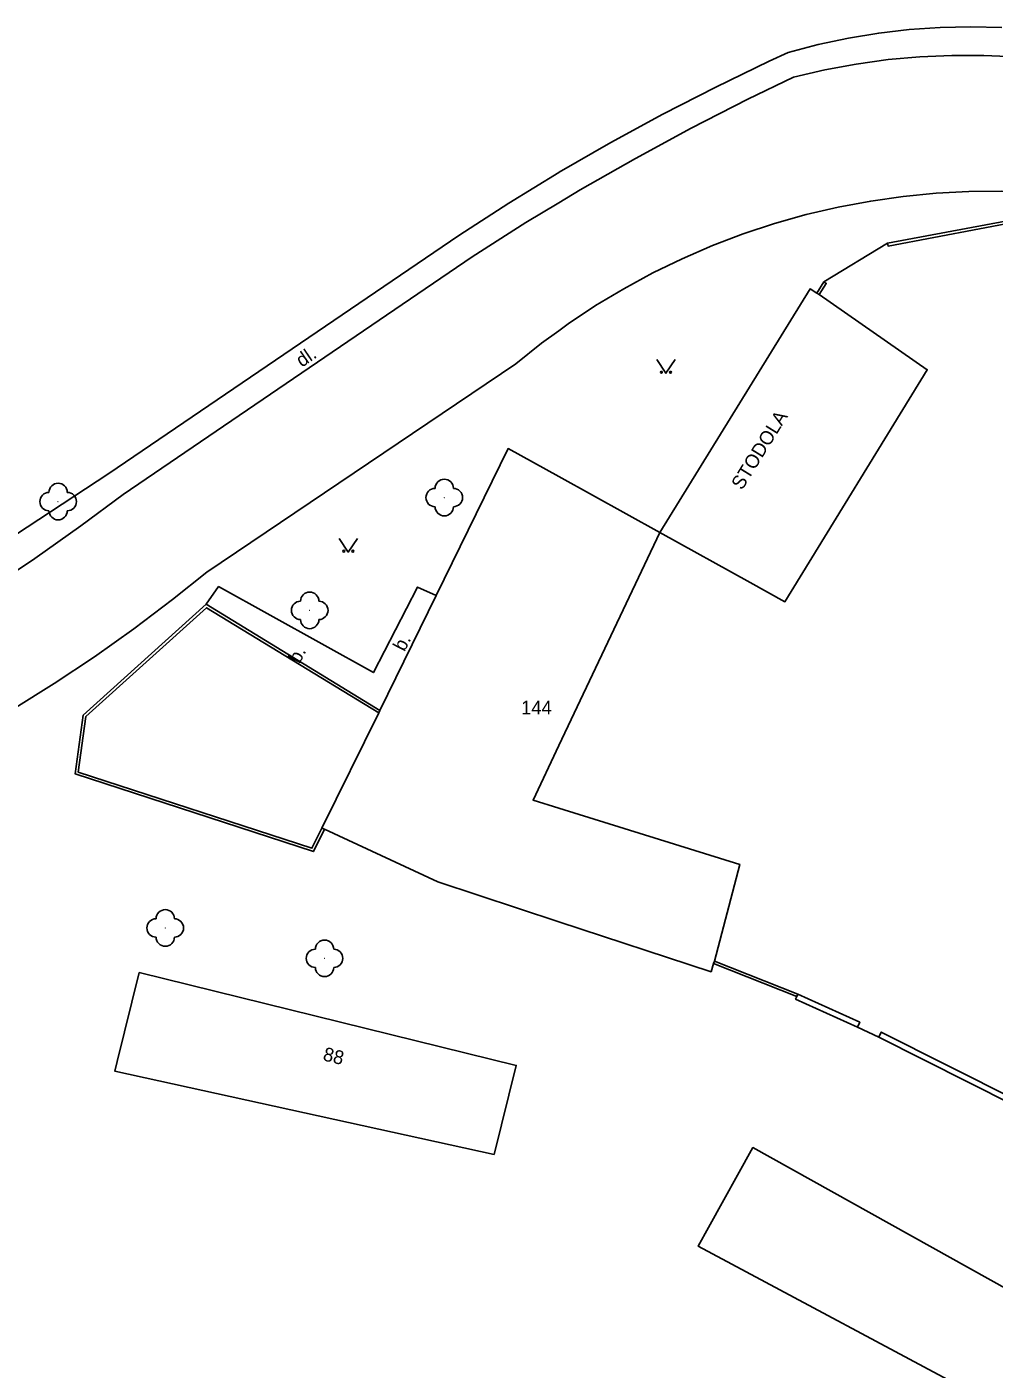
# Model space of a CAD drawing. Extents: x -582162 to -561283, y -1187583 to -1183539.
# Drawn here: x -570029.1 to -569976.2, y -1185373.8 to -1185300.5 of the extents above; entities that cross this region are included whole.
import ezdxf

# ---------------------------------------------------------------- set-up
doc = ezdxf.new("R2010")
doc.units = 0
for name, color, linetype in [('Vrstva 1', 7, 'Continuous'), ('Vrstva 10', 7, 'Continuous'), ('Vrstva 11', 7, 'Continuous'), ('Vrstva 14', 7, 'Continuous'), ('Vrstva 3', 7, 'Continuous'), ('Vrstva 4', 7, 'Continuous'), ('Vrstva 5', 7, 'Continuous'), ('Vrstva 6', 7, 'Continuous'), ('Vrstva 9', 7, 'Continuous')]:
    doc.layers.add(name, color=color, linetype=linetype)

# ---------------------------------------------------------------- blocks, each defined once
blk = doc.blocks.new('3.130')
at = {"layer": 'Vrstva 1'}
blk.add_circle((0, 0), 0.001, dxfattribs=at)
for centre, start, end in [((0, 1), 0, 180), ((-1, 0), 90, 270), ((1, 0), 270, 90), ((0, -1), 180, 360)]:
    blk.add_arc(centre, 1, start, end, dxfattribs=at)
blk = doc.blocks.new('3.140')
at = {"layer": 'Vrstva 1'}
blk.add_lwpolyline([(-1, 1.5), (0, 0), (1, 1.5)], dxfattribs=at)
for centre in [(-0.5, 0.1), (0.5, 0.1)]:
    blk.add_circle(centre, 0.1, dxfattribs=at)

msp = doc.modelspace()

# ---------------------------------------------------------------- linework, layer by layer
at = {"layer": 'Vrstva 10'}
for points in [[(-570000, -1185308.46), (-569999.98, -1185308.45), (-569997.17, -1185306.83), (-569994.32, -1185305.28), (-569991.43, -1185303.8), (-569988.51, -1185302.39), (-569987.47, -1185301.91), (-569985.84, -1185301.48), (-569984.19, -1185301.13), (-569982.53, -1185300.85), (-569980.86, -1185300.66), (-569979.18, -1185300.54), (-569977.5, -1185300.51), (-569975.81, -1185300.55)], [(-570000, -1185310.12), (-569998.83, -1185309.41), (-569995.82, -1185307.69), (-569992.77, -1185306.04), (-569989.68, -1185304.46), (-569987.18, -1185303.25), (-569985.48, -1185302.86), (-569983.76, -1185302.54), (-569982.02, -1185302.3), (-569980.28, -1185302.14), (-569978.54, -1185302.07), (-569976.79, -1185302.07), (-569975.04, -1185302.15)], [(-570042.37, -1185336.1), (-570037.35, -1185333.27), (-570024.58, -1185324.9), (-570005.47, -1185311.9), (-570002.74, -1185310.14), (-570000, -1185308.46)], [(-570000, -1185317.1), (-569999.49, -1185316.73), (-569998, -1185315.73), (-569996.45, -1185314.81), (-569994.87, -1185313.95), (-569993.26, -1185313.17), (-569991.61, -1185312.45), (-569989.93, -1185311.81), (-569988.22, -1185311.25), (-569986.49, -1185310.76), (-569984.74, -1185310.35), (-569982.97, -1185310.02), (-569981.19, -1185309.77), (-569979.4, -1185309.6), (-569977.6, -1185309.5), (-569975.81, -1185309.49), (-569974.01, -1185309.56), (-569972.22, -1185309.71), (-569970.43, -1185309.93), (-569968.66, -1185310.24), (-569966.9, -1185310.62), (-569965.21, -1185311.07)], [(-570041.84, -1185337.36), (-570039.12, -1185335.93), (-570036.43, -1185334.44), (-570033.79, -1185332.87), (-570031.18, -1185331.23), (-570028.62, -1185329.53), (-570026.11, -1185327.76), (-570023.8, -1185326.05), (-570004.73, -1185313.06), (-570001.8, -1185311.2), (-570000, -1185310.12)], [(-570036.78, -1185341.53), (-570034.42, -1185340.34), (-570032.1, -1185339.09), (-570029.81, -1185337.76), (-570027.56, -1185336.37), (-570025.36, -1185334.9), (-570023.21, -1185333.38), (-570021.1, -1185331.78), (-570019.22, -1185330.28), (-570002.35, -1185318.91), (-570000.95, -1185317.79), (-570000, -1185317.1)], [(-570019.26, -1185332.04), (-570018.59, -1185331.07), (-570010.13, -1185335.77), (-570007.73, -1185331.1), (-570006.7, -1185331.55)]]:
    msp.add_lwpolyline(points, dxfattribs=at)
at = {"layer": 'Vrstva 4'}
for points in [[(-569994.49, -1185328.12), (-569986.28, -1185314.82), (-569985.91, -1185315.05)], [(-569985.91, -1185315.05), (-569985.78, -1185315.13)], [(-570006.7, -1185331.55), (-570002.77, -1185323.54), (-570000, -1185325.07)], [(-570000, -1185325.07), (-569994.49, -1185328.12)], [(-569994.49, -1185328.12), (-569989.56, -1185330.84)], [(-570009.78, -1185337.83), (-570006.7, -1185331.55)], [(-570012.94, -1185344.26), (-570009.84, -1185337.96)], [(-570009.84, -1185337.96), (-570009.78, -1185337.83)], [(-570012.8, -1185344.32), (-570012.94, -1185344.26)], [(-570000, -1185349.37), (-570006.62, -1185347.19), (-570012.8, -1185344.32)], [(-569991.55, -1185351.66), (-569991.69, -1185352.1), (-570000, -1185349.37)], [(-570024.12, -1185357), (-570022.92, -1185352.15)], [(-570022.92, -1185352.15), (-570002.33, -1185357.22), (-570003.53, -1185362.08)], [(-569991.5, -1185351.52), (-569991.55, -1185351.66)], [(-569991.83, -1185366.07), (-569989.4, -1185361.7), (-569967.85, -1185373.71), (-569970.53, -1185379.24)]]:
    msp.add_lwpolyline(points, dxfattribs=at)
at = {"layer": 'Vrstva 5'}
for points in [[(-569985.78, -1185315.13), (-569979.88, -1185319.23), (-569987.65, -1185331.9), (-569989.56, -1185330.84)], [(-570000, -1185339.75), (-569994.49, -1185328.12)], [(-570000, -1185343.17), (-570001.41, -1185342.73), (-570000, -1185339.75)], [(-569991.5, -1185351.52), (-569990.11, -1185346.24), (-570000, -1185343.17)], [(-570003.53, -1185362.08), (-570024.25, -1185357.53), (-570024.12, -1185357)], [(-569980.48, -1185388.31), (-569982.6, -1185387.28), (-569976.38, -1185375.64), (-569992.4, -1185367.08), (-569991.83, -1185366.07)]]:
    msp.add_lwpolyline(points, dxfattribs=at)
at = {"layer": 'Vrstva 9'}
for points in [[(-569982.05, -1185312.33), (-569974.54, -1185310.92), (-569965.38, -1185311.99), (-569949.98, -1185322.67)], [(-569982.05, -1185312.33), (-569982.02, -1185312.48), (-569974.54, -1185311.07), (-569965.44, -1185312.14), (-569950.06, -1185322.79)], [(-569982.05, -1185312.33), (-569985.53, -1185314.44)], [(-569985.91, -1185315.05), (-569985.53, -1185314.44)], [(-569985.53, -1185314.44), (-569985.4, -1185314.52), (-569985.78, -1185315.13)], [(-570012.8, -1185344.32), (-570013.41, -1185345.54), (-570026.42, -1185341.3), (-570025.98, -1185338.09), (-570019.26, -1185332.04)], [(-570012.94, -1185344.26), (-570013.49, -1185345.36), (-570026.25, -1185341.2), (-570025.84, -1185338.17), (-570019.24, -1185332.23), (-570009.84, -1185337.96)], [(-570019.26, -1185332.04), (-570009.78, -1185337.83)], [(-569987.01, -1185353.45), (-569991.55, -1185351.66)], [(-569986.95, -1185353.32), (-569991.5, -1185351.52)], [(-569987.01, -1185353.45), (-569987.07, -1185353.59), (-569983.69, -1185355.13)], [(-569986.95, -1185353.32), (-569987.01, -1185353.45)], [(-569983.69, -1185355.13), (-569983.57, -1185354.86), (-569986.95, -1185353.32)], [(-569983.69, -1185355.13), (-569982.52, -1185355.67)], [(-569972.35, -1185360.66), (-569975.05, -1185359.1), (-569982.39, -1185355.4), (-569982.52, -1185355.67)], [(-569982.52, -1185355.67), (-569975.19, -1185359.36), (-569972.5, -1185360.92)]]:
    msp.add_lwpolyline(points, dxfattribs=at)

# ---------------------------------------------------------------- block references
at = {"layer": 'Vrstva 11', "xscale": 0.5, "yscale": 0.5}
for p in [(-570027.35, -1185326.43), (-570006.26, -1185326.21), (-570013.61, -1185332.37), (-570021.5, -1185349.71), (-570012.8, -1185351.37)]:
    msp.add_blockref('3.130', p, dxfattribs=at)
at = {"layer": 'Vrstva 3', "xscale": 0.5, "yscale": 0.5}
for p in [(-569994.15, -1185319.42), (-570011.5, -1185329.19)]:
    msp.add_blockref('3.140', p, dxfattribs=at)

# ---------------------------------------------------------------- texts
at = {"layer": 'Vrstva 14'}
for s, rotation, p in [(' dl.', 34.226, (-570014.27, -1185319.28)), (' STODOLA', 58.297, (-569990.14, -1185326.08)), (' b.', 62.801, (-570008.56, -1185334.91)), (' b.', 62.801, (-570014.29, -1185335.57))]:
    msp.add_text(s, height=0.75, rotation=rotation, dxfattribs=at).set_placement(p)
at = {"layer": 'Vrstva 6'}
msp.add_text('144', height=0.75, dxfattribs=at).set_placement((-570002.06, -1185338.05))
msp.add_text('88', height=0.75, rotation=346.167, dxfattribs=at).set_placement((-570012.93, -1185356.93))

doc.saveas('drawing.dxf')
